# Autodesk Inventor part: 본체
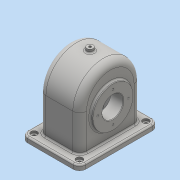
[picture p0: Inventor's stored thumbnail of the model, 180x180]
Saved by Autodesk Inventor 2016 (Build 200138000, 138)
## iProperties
Created: 2018-11
Part Number: 본체
Material: 일반
Document SubType Name: Modeling
Designer: user
Mass: 404.348 g
Surface Area: 1182.97 cm^2
Volume: 404.348 cm^3
Density: 1 g/cm^3
Appearance: 기본값
Author: user
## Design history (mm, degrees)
sketch "스케치1"
  geometry: L1 (-55, -75)-(55, -75); L2 (55, -75)-(55, 75); L3 (55, 75)-(-55, 75); L4 (-55, 75)-(-55, -75); L5 (-55, -75)-(55, 75); L6 (55, -75)-(-55, 75); 1 further point
  constraints: 12 end point, 2 midpoint, 2 parallel, 1 horizontal, 1 perpendicular
  dimensions: "d0" = 110 distance of L3.end L2.end; "d1" = 150 distance of L2.end L1.end
extrude "돌출1" new body sketch "스케치1" distance "d2" = 10; taper "d3" = 0 deg
fillet "모깎기1" dims "d4" = 12
sketch "스케치2"
  geometry: L1 (-58, 78)-(-58, 0); L2 (63, 0)-(-63, 0) reference; L3 (58, 78)-(58, 0); L4 (-58, 0)-(58, 0); A1 r 58 centre (0, 78) between (-58, 78) and (58, 78); 2 further points
  constraints: 6 end point, 2 point on circle, 2 point on line, 1 centre point, 1 horizontal, 1 midpoint, 1 perpendicular, 1 tangent, 1 vertical, 1 vertical alignment
  dimensions: "d5" = 116 diameter of A1; "d6" = 78 distance from line of L2 A1.centre; "d7" = 78 distance of L1.start L1.end
extrude "돌출2" join sketch "스케치2" stored distance "d8" = 77; taper "d9" = 0 deg
feature "쉘1" dims "d10" = 6, "d11" = 10, "d12" = 5
fillet "모깎기2" dims "d13" = 13
fillet "모깎기3" dims "d14" = 8
sketch "스케치3"
  geometry: L1 (0, 63)-(0, -63) reference; C1 r 38 at (65, 0); 2 further points
  constraints: 1 centre point, 1 horizontal alignment, 1 midpoint
  dimensions: "d15" = 76 diameter of C1; "d16" = 65 distance from line of L1 C1.centre
extrude "돌출3" join sketch "스케치3" distance "d17" = 10; taper "d18" = 0 deg
sketch "스케치4"
  geometry: L1 (0, -63)-(0, 63) reference; C1 r 38 at (-65, 0); 2 further points
  constraints: 1 centre point, 1 horizontal alignment, 1 midpoint
  dimensions: "d19" = 76 diameter of C1; "d20" = 65 distance from line of L1 C1.centre
extrude "돌출4" join sketch "스케치4" distance "d21" = 5; taper "d22" = 0 deg
sketch "스케치5"
  geometry: C1 r 20 at (0, 0); C2 r 38 at (0, 0) reference; 1 further point
  constraints: 1 centre point, 1 concentric
  dimensions: "d23" = 40 diameter of C1
extrude "돌출5" cut sketch "스케치5" stored distance "d24" = 5; taper "d25" = 0 deg
sketch "스케치6"
  geometry: L1 (-43.5, 103)-(-43.5, 27) reference; L2 (-43.5, 65)-(-19.5, 65); L3 (-19.5, 65)-(-19.5, 93); L4 (-19.5, 93)-(-38.5, 108.943); L5 (-38.5, 78)-(-38.5, 123) reference; L6 (-38.5, 10)-(-38.5, 78) reference; L7 (-38.5, 108.943)-(-38.5, 65); 1 further point
  constraints: 8 end point, 3 point on line, 1 horizontal, 1 midpoint, 1 vertical
  dimensions: "d26" = 24 distance of L2.start L2.end; "d27" = 28 distance of L2.end L3.end; "d28" = 50 deg angle of L3 L4
revolve "회전1" sketch "스케치6" stored, may be unused: angle "d29" = 90 deg
sketch "스케치7"
  geometry: C1 r 20 at (0, 0); C2 r 20 at (0, 0) reference; 1 further point
  constraints: 1 centre point, 1 concentric
  dimensions: "d30" = 40 diameter of C1
extrude "돌출6" cut sketch "스케치7" stored distance "d31" = 24; taper "d32" = 0 deg
node "작업 평면1"
sketch "스케치8"
  geometry: C1 r 6 at (0, 0); 1 further point
  constraints: 1 centre point, 1 coincident
  dimensions: "d34" = 12 diameter of C1
extrude "돌출7" join sketch "스케치8" stored distance "d35" = 24; taper "d36" = 0 deg
feature "면 기울기1" dims angle "d37" = 5 deg
sketch "스케치9"
  geometry: 2 further points
  constraints: 1 coincident
hole "구멍1" sketch "스케치9" at (0, 0) diameter "d38" = 4.459; stored, may be unused: countersink angle "d42" = 90 deg, drill point angle "d44" = 118 deg; dims "d39" = 10, "d40" = 4, "d41" = 2, "d43" = 12.8
sketch "스케치10"
  geometry: L1 (-29, 0)-(29, 0); C1 r 20 at (0, 0) reference; A1 r 29 centre (0, 0) between (-29, 0) and (29, 0); 2 further points
  constraints: 2 end point, 2 point on circle, 1 centre point, 1 coincident, 1 concentric, 1 horizontal
  dimensions: "d45" = 58 diameter of A1; "d46" = 58 distance of L1.start L1.end
hole "구멍2" sketch "스케치10" at (-29, 0) diameter "d47" = 3.242; stored, may be unused: countersink angle "d51" = 90 deg, drill point angle "d53" = 118 deg; dims "d48" = 8, "d49" = 4, "d50" = 2, "d52" = 10
sketch "스케치11" dims "d57" = 58
  geometry: L1 (29, 0)-(-29, 0); C1 r 38 at (0, 0) reference; C2 r 1.621 at (-29, 0) reference; 3 further points
  constraints: 2 end point, 1 coincident, 1 horizontal, 1 horizontal alignment, 3 other
hole "구멍3" sketch "스케치11" at (29, 0) diameter "d58" = 3.242; stored, may be unused: countersink angle "d62" = 90 deg, drill point angle "d64" = 118 deg; dims "d59" = 8, "d60" = 4, "d61" = 2, "d63" = 10
sketch "스케치12"
  geometry: C1 r 6 at (-43, -63); A1 r 12 centre (-43, -63) between (-55, -63) and (-43, -75) reference; 1 further point
  constraints: 1 centre point, 1 concentric
  dimensions: "d68" = 12 diameter of C1
extrude "돌출8" cut sketch "스케치12" distance "d69" = 4; taper "d70" = 0 deg
sketch "스케치13"
  geometry: C1 r 2.5 at (0, 0); C2 r 6 at (0, 0) reference; 1 further point
  constraints: 1 centre point, 1 concentric
  dimensions: "d71" = 5 diameter of C1
extrude "돌출9" cut sketch "스케치13" stored distance "d72" = 4; taper "d73" = 0 deg
fillet "모깎기4" dims "d74" = 3
chamfer "모따기1" distance "d75" = 1; stored, may be unused: second distance "d76" = 2, angle "d77" = 45 deg
sketch "스케치14"
  geometry: L1 (64, 0)-(64, 65) reference; L2 (68.5, 78)-(-17.5, 78) reference; 2 further points
  constraints: 1 other
  dimensions: "d78" = 38.5 distance from line of L1 point (25.5, 38); "d79" = 40 distance from line of L2 point (25.5, 38)
feature "엠보싱1" sketch "스케치14" dims "d80" = 0.5, "d81" = 0
fillet "모깎기5" dims "d82" = 3
fillet "모깎기6" dims "d83" = 3
node "솔리드1"
pattern_circular "원형 패턴1" dims angle "d55" = 360 deg
pattern_circular "원형 패턴2" dims angle "d66" = 360 deg
mirror "대칭1"
mirror "대칭2"
other parameters: "d33" = 142
